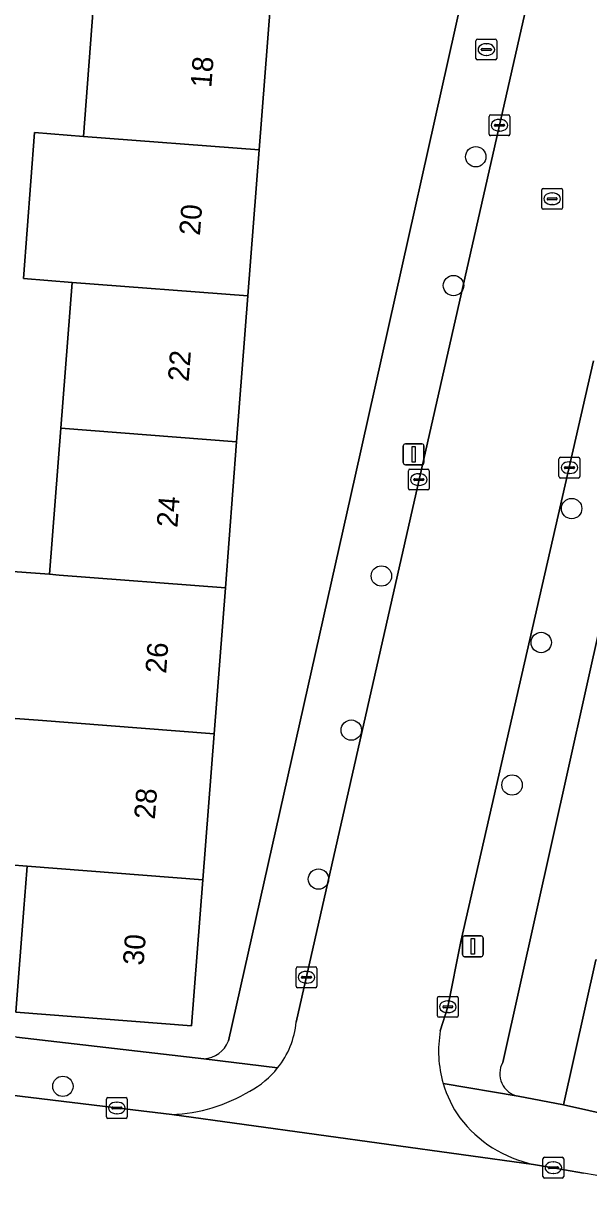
# Model space of a CAD drawing. Extents: x 161838 to 162344, y 381620 to 382160.
# Drawn here: x 161984.1 to 162011.2, y 381777.3 to 381833 of the extents above; entities that cross this region are included whole.
import ezdxf

# ---------------------------------------------------------------- set-up
doc = ezdxf.new("R2010")
doc.units = 0
for name, color, linetype in [('IMGEO_Boom', 7, 'Continuous'), ('IMGEO_Brandkraan', 7, 'Continuous'), ('IMGEO_Erf', 7, 'Continuous'), ('IMGEO_Kolk', 7, 'Continuous'), ('IMGEO_Lichtmast', 7, 'Continuous'), ('IMGEO_Pand', 7, 'Continuous'), ('IMGEO_Pand_nummerreeks', 7, 'Continuous'), ('IMGEO_Rijbaan_lokaal_open', 7, 'Continuous'), ('IMGEO_Rioolput', 7, 'Continuous'), ('IMGEO_Voetpad_open', 7, 'Continuous')]:
    doc.layers.add(name, color=color, linetype=linetype)

msp = doc.modelspace()

# ---------------------------------------------------------------- linework, layer by layer
at = {"layer": 'IMGEO_Boom'}
for centre in [(162005.785, 381826.594), (162004.716, 381820.404), (162010.388, 381809.695), (162001.255, 381806.458), (162008.926, 381803.263), (161999.811, 381799.055), (162007.527, 381796.419), (161998.235, 381791.9), (161985.966, 381781.945)]:
    msp.add_circle(centre, 0.489, dxfattribs=at)
at = {"layer": 'IMGEO_Brandkraan'}
for p, q in [((162005.793, 381831.316), (162005.793, 381832.168)), ((162005.868, 381832.242), (162006.72, 381832.242)), ((162006.281, 381832.022), (162006.306, 381832.022)), ((162006.794, 381832.168), (162006.794, 381831.316)), ((162006.052, 381831.736), (162006.052, 381831.748)), ((162006.49, 381831.699), (162006.092, 381831.699)), ((162006.095, 381831.785), (162006.493, 381831.785)), ((162006.304, 381831.462), (162006.279, 381831.462)), ((162006.536, 381831.748), (162006.536, 381831.736)), ((162006.72, 381831.242), (162005.868, 381831.242))]:
    msp.add_line(p, q, dxfattribs=at)
for points in [[(162005.793, 381831.316), (162005.793, 381832.168)], [(162005.868, 381832.242), (162006.72, 381832.242)], [(162006.794, 381832.168), (162006.794, 381831.316)], [(162006.72, 381831.242), (162005.868, 381831.242)]]:
    msp.add_lwpolyline(points, dxfattribs=at)
for centre, radius, start, end in [((162005.87, 381832.166), 0.0765, 91.552, 178.448), ((162005.87, 381832.166), 0.0765, 91.552, 178.448), ((162006.718, 381832.166), 0.0765, 1.552, 88.448), ((162006.718, 381832.166), 0.0765, 1.552, 88.448), ((162006.092, 381831.745), 0.0403, 85.8775, 175.7526), ((162006.089, 381831.735), 0.0366, 178.938, 274.7102), ((162006.493, 381831.742), 0.043, 264.8664, 352.4533), ((162006.497, 381831.747), 0.0386, 1.7309, 96.639), ((162005.87, 381831.318), 0.0765, 181.552, 268.448), ((162005.87, 381831.318), 0.0765, 181.552, 268.448), ((162006.718, 381831.318), 0.0765, 271.552, 358.448), ((162006.718, 381831.318), 0.0765, 271.552, 358.448)]:
    msp.add_arc(centre, radius, start, end, dxfattribs=at)
for centre, major_axis, ratio, start_param, end_param in [((162006.28, 381831.742), (-0.387, 0.002), 0.722429, 4.712389, 7.853982), ((162006.305, 381831.742), (-0.39, 0.002), 0.717154, 1.570796, 4.712389)]:
    msp.add_ellipse(centre, major_axis=major_axis, ratio=ratio, start_param=start_param, end_param=end_param, dxfattribs=at)
at = {"layer": 'IMGEO_Erf'}
for points in [[(161993.909, 381784.124), (162000, 381811.259), (162006.057, 381838.422), (162012.585, 381866.816)], [(161982.867, 381806.728), (161985.326, 381806.539), (161985.867, 381813.55), (161986.408, 381820.561), (161984.068, 381820.741), (161984.608, 381827.752), (161986.949, 381827.572), (161987.489, 381834.583)], [(161995.929, 381833.933), (161995.389, 381826.922), (161994.848, 381819.911), (161994.307, 381812.899), (161993.766, 381805.889), (161993.225, 381798.877), (161992.684, 381791.867), (161992.143, 381784.853), (161983.703, 381785.505), (161984.088, 381790.491), (161984.228, 381792.307), (161984.244, 381792.516), (161981.789, 381792.705)], [(162044.543, 381799.981), (162042.031, 381801.108), (162037.412, 381803.181), (162036.567, 381801.299), (162036.274, 381800.646), (162035.005, 381801.215), (162035.349, 381801.982), (162035.257, 381802.025), (162033.675, 381798.452), (162031.409, 381799.456), (162032.996, 381803.041), (162032.026, 381803.471), (162033.149, 381806.008), (162030.965, 381806.988), (162033.435, 381812.491), (162032.192, 381813.086), (162018.867, 381816.056), (162015.883, 381816.441), (162014.199, 381815.078), (162007.085, 381783.093)], [(162007.821, 381781.474), (162009.992, 381781.058), (162011.554, 381788.029)], [(161983.732, 381784.311), (161992.738, 381783.267)]]:
    msp.add_lwpolyline(points, dxfattribs=at)
for centre, radius, start, end in [((161992.665, 381784.595), 1.33, 273.1399, 339.2574), ((162008.018, 381782.54), 1.084, 149.35, 259.5432)]:
    msp.add_arc(centre, radius, start, end, dxfattribs=at)
at = {"layer": 'IMGEO_Kolk'}
for p, q in [((162006.499, 381828.606), (162007.351, 381828.606)), ((162006.424, 381827.68), (162006.424, 381828.532)), ((162006.683, 381828.1), (162006.683, 381828.112)), ((162007.121, 381828.063), (162006.723, 381828.063)), ((162006.726, 381828.149), (162007.124, 381828.149)), ((162006.912, 381828.386), (162006.937, 381828.386)), ((162007.167, 381828.112), (162007.167, 381828.1)), ((162007.425, 381828.532), (162007.425, 381827.68)), ((162007.351, 381827.606), (162006.499, 381827.606)), ((162006.935, 381827.826), (162006.91, 381827.826)), ((162009.781, 381811.234), (162009.781, 381812.086)), ((162009.856, 381812.16), (162010.708, 381812.16)), ((162010.269, 381811.94), (162010.294, 381811.94)), ((162010.782, 381812.086), (162010.782, 381811.234)), ((162002.552, 381810.662), (162002.552, 381811.514)), ((162002.627, 381811.588), (162003.479, 381811.588)), ((162003.04, 381811.368), (162003.065, 381811.368)), ((162003.553, 381811.514), (162003.553, 381810.662)), ((162010.04, 381811.654), (162010.04, 381811.666)), ((162010.478, 381811.617), (162010.08, 381811.617)), ((162010.083, 381811.703), (162010.481, 381811.703)), ((162010.292, 381811.38), (162010.267, 381811.38)), ((162010.524, 381811.666), (162010.524, 381811.654)), ((162002.811, 381811.082), (162002.811, 381811.094)), ((162003.249, 381811.045), (162002.851, 381811.045)), ((162002.854, 381811.131), (162003.252, 381811.131)), ((162003.063, 381810.808), (162003.038, 381810.808)), ((162003.295, 381811.094), (162003.295, 381811.082)), ((162010.708, 381811.16), (162009.856, 381811.16)), ((162003.479, 381810.588), (162002.627, 381810.588)), ((161997.16, 381786.758), (161997.16, 381787.61)), ((161997.235, 381787.684), (161998.087, 381787.684)), ((161997.648, 381787.464), (161997.673, 381787.464)), ((161998.161, 381787.61), (161998.161, 381786.758)), ((161997.419, 381787.178), (161997.419, 381787.19)), ((161997.857, 381787.141), (161997.459, 381787.141)), ((161997.462, 381787.227), (161997.86, 381787.227)), ((161997.671, 381786.904), (161997.646, 381786.904)), ((161997.903, 381787.19), (161997.903, 381787.178)), ((161998.087, 381786.684), (161997.235, 381786.684)), ((162004.021, 381786.265), (162004.873, 381786.265)), ((162003.946, 381785.339), (162003.946, 381786.191)), ((162004.205, 381785.759), (162004.205, 381785.771)), ((162004.643, 381785.722), (162004.245, 381785.722)), ((162004.248, 381785.808), (162004.646, 381785.808)), ((162004.434, 381786.045), (162004.459, 381786.045)), ((162004.689, 381785.771), (162004.689, 381785.759)), ((162004.947, 381786.191), (162004.947, 381785.339)), ((162004.873, 381785.265), (162004.021, 381785.265)), ((162004.457, 381785.485), (162004.432, 381785.485)), ((161988.055, 381780.481), (161988.055, 381781.333)), ((161988.13, 381781.407), (161988.982, 381781.407)), ((161989.056, 381781.333), (161989.056, 381780.481)), ((161988.314, 381780.901), (161988.314, 381780.913)), ((161988.752, 381780.864), (161988.354, 381780.864)), ((161988.357, 381780.95), (161988.755, 381780.95)), ((161988.543, 381781.187), (161988.568, 381781.187)), ((161988.798, 381780.913), (161988.798, 381780.901)), ((161988.982, 381780.407), (161988.13, 381780.407)), ((161988.566, 381780.627), (161988.541, 381780.627)), ((162009.009, 381777.612), (162009.009, 381778.464)), ((162009.084, 381778.538), (162009.936, 381778.538)), ((162010.01, 381778.464), (162010.01, 381777.612)), ((162009.268, 381778.032), (162009.268, 381778.044)), ((162009.706, 381777.995), (162009.308, 381777.995)), ((162009.311, 381778.081), (162009.709, 381778.081)), ((162009.497, 381778.318), (162009.522, 381778.318)), ((162009.752, 381778.044), (162009.752, 381778.032)), ((162009.936, 381777.538), (162009.084, 381777.538)), ((162009.52, 381777.758), (162009.495, 381777.758))]:
    msp.add_line(p, q, dxfattribs=at)
for points in [[(162006.499, 381828.606), (162007.351, 381828.606)], [(162006.424, 381827.68), (162006.424, 381828.532)], [(162007.425, 381828.532), (162007.425, 381827.68)], [(162007.351, 381827.606), (162006.499, 381827.606)], [(162009.781, 381811.234), (162009.781, 381812.086)], [(162009.856, 381812.16), (162010.708, 381812.16)], [(162010.782, 381812.086), (162010.782, 381811.234)], [(162002.552, 381810.662), (162002.552, 381811.514)], [(162002.627, 381811.588), (162003.479, 381811.588)], [(162003.553, 381811.514), (162003.553, 381810.662)], [(162010.708, 381811.16), (162009.856, 381811.16)], [(162003.479, 381810.588), (162002.627, 381810.588)], [(161997.16, 381786.758), (161997.16, 381787.61)], [(161997.235, 381787.684), (161998.087, 381787.684)], [(161998.161, 381787.61), (161998.161, 381786.758)], [(161998.087, 381786.684), (161997.235, 381786.684)], [(162004.021, 381786.265), (162004.873, 381786.265)], [(162003.946, 381785.339), (162003.946, 381786.191)], [(162004.947, 381786.191), (162004.947, 381785.339)], [(162004.873, 381785.265), (162004.021, 381785.265)], [(161988.055, 381780.481), (161988.055, 381781.333)], [(161988.13, 381781.407), (161988.982, 381781.407)], [(161989.056, 381781.333), (161989.056, 381780.481)], [(161988.982, 381780.407), (161988.13, 381780.407)], [(162009.009, 381777.612), (162009.009, 381778.464)], [(162009.084, 381778.538), (162009.936, 381778.538)], [(162010.01, 381778.464), (162010.01, 381777.612)], [(162009.936, 381777.538), (162009.084, 381777.538)]]:
    msp.add_lwpolyline(points, dxfattribs=at)
for centre, radius, start, end in [((162006.501, 381828.53), 0.0765, 91.552, 178.448), ((162006.501, 381828.53), 0.0765, 91.552, 178.448), ((162007.349, 381828.53), 0.0765, 1.552, 88.448), ((162007.349, 381828.53), 0.0765, 1.552, 88.448), ((162006.723, 381828.109), 0.0403, 85.8775, 175.7526), ((162006.72, 381828.099), 0.0366, 178.938, 274.7102), ((162007.124, 381828.106), 0.043, 264.8664, 352.4533), ((162007.128, 381828.111), 0.0386, 1.7309, 96.639), ((162006.501, 381827.682), 0.0765, 181.552, 268.448), ((162006.501, 381827.682), 0.0765, 181.552, 268.448), ((162007.349, 381827.682), 0.0765, 271.552, 358.448), ((162007.349, 381827.682), 0.0765, 271.552, 358.448), ((162009.858, 381812.084), 0.0765, 91.552, 178.448), ((162009.858, 381812.084), 0.0765, 91.552, 178.448), ((162010.706, 381812.084), 0.0765, 1.552, 88.448), ((162010.706, 381812.084), 0.0765, 1.552, 88.448), ((162002.629, 381811.512), 0.0765, 91.552, 178.448), ((162002.629, 381811.512), 0.0765, 91.552, 178.448), ((162003.477, 381811.512), 0.0765, 1.552, 88.448), ((162003.477, 381811.512), 0.0765, 1.552, 88.448), ((162010.08, 381811.663), 0.0403, 85.8775, 175.7526), ((162010.077, 381811.653), 0.0366, 178.938, 274.7102), ((162010.481, 381811.66), 0.043, 264.8664, 352.4533), ((162010.485, 381811.665), 0.0386, 1.7309, 96.639), ((162002.851, 381811.091), 0.0403, 85.8775, 175.7526), ((162002.848, 381811.081), 0.0366, 178.938, 274.7102), ((162003.252, 381811.088), 0.043, 264.8664, 352.4533), ((162003.256, 381811.093), 0.0386, 1.7309, 96.639), ((162009.858, 381811.236), 0.0765, 181.552, 268.448), ((162009.858, 381811.236), 0.0765, 181.552, 268.448), ((162010.706, 381811.236), 0.0765, 271.552, 358.448), ((162010.706, 381811.236), 0.0765, 271.552, 358.448), ((162002.629, 381810.664), 0.0765, 181.552, 268.448), ((162002.629, 381810.664), 0.0765, 181.552, 268.448), ((162003.477, 381810.664), 0.0765, 271.552, 358.448), ((162003.477, 381810.664), 0.0765, 271.552, 358.448), ((161997.237, 381787.608), 0.0765, 91.552, 178.448), ((161997.237, 381787.608), 0.0765, 91.552, 178.448), ((161998.085, 381787.608), 0.0765, 1.552, 88.448), ((161998.085, 381787.608), 0.0765, 1.552, 88.448), ((161997.459, 381787.187), 0.0403, 85.8775, 175.7526), ((161997.456, 381787.177), 0.0366, 178.938, 274.7102), ((161997.86, 381787.184), 0.043, 264.8664, 352.4533), ((161997.864, 381787.189), 0.0386, 1.7309, 96.639), ((161997.237, 381786.76), 0.0765, 181.552, 268.448), ((161997.237, 381786.76), 0.0765, 181.552, 268.448), ((161998.085, 381786.76), 0.0765, 271.552, 358.448), ((161998.085, 381786.76), 0.0765, 271.552, 358.448), ((162004.023, 381786.189), 0.0765, 91.552, 178.448), ((162004.023, 381786.189), 0.0765, 91.552, 178.448), ((162004.871, 381786.189), 0.0765, 1.552, 88.448), ((162004.871, 381786.189), 0.0765, 1.552, 88.448), ((162004.245, 381785.768), 0.0403, 85.8775, 175.7526), ((162004.242, 381785.758), 0.0366, 178.938, 274.7102), ((162004.646, 381785.765), 0.043, 264.8664, 352.4533), ((162004.65, 381785.77), 0.0386, 1.7309, 96.639), ((162004.023, 381785.341), 0.0765, 181.552, 268.448), ((162004.023, 381785.341), 0.0765, 181.552, 268.448), ((162004.871, 381785.341), 0.0765, 271.552, 358.448), ((162004.871, 381785.341), 0.0765, 271.552, 358.448), ((161988.132, 381781.331), 0.0765, 91.552, 178.448), ((161988.132, 381781.331), 0.0765, 91.552, 178.448), ((161988.98, 381781.331), 0.0765, 1.552, 88.448), ((161988.98, 381781.331), 0.0765, 1.552, 88.448), ((161988.354, 381780.91), 0.0403, 85.8775, 175.7526), ((161988.351, 381780.9), 0.0366, 178.938, 274.7102), ((161988.755, 381780.907), 0.043, 264.8664, 352.4533), ((161988.759, 381780.912), 0.0386, 1.7309, 96.639), ((161988.132, 381780.483), 0.0765, 181.552, 268.448), ((161988.132, 381780.483), 0.0765, 181.552, 268.448), ((161988.98, 381780.483), 0.0765, 271.552, 358.448), ((161988.98, 381780.483), 0.0765, 271.552, 358.448), ((162009.086, 381778.462), 0.0765, 91.552, 178.448), ((162009.086, 381778.462), 0.0765, 91.552, 178.448), ((162009.934, 381778.462), 0.0765, 1.552, 88.448), ((162009.934, 381778.462), 0.0765, 1.552, 88.448), ((162009.308, 381778.041), 0.0403, 85.8775, 175.7526), ((162009.305, 381778.031), 0.0366, 178.938, 274.7102), ((162009.709, 381778.038), 0.043, 264.8664, 352.4533), ((162009.713, 381778.043), 0.0386, 1.7309, 96.639), ((162009.086, 381777.614), 0.0765, 181.552, 268.448), ((162009.086, 381777.614), 0.0765, 181.552, 268.448), ((162009.934, 381777.614), 0.0765, 271.552, 358.448), ((162009.934, 381777.614), 0.0765, 271.552, 358.448)]:
    msp.add_arc(centre, radius, start, end, dxfattribs=at)
for centre, major_axis, ratio, start_param, end_param in [((162006.911, 381828.106), (-0.387, 0.002), 0.722429, 4.712389, 7.853982), ((162006.936, 381828.106), (-0.39, 0.002), 0.717154, 1.570796, 4.712389), ((162010.268, 381811.66), (-0.387, 0.002), 0.722429, 4.712389, 7.853982), ((162010.293, 381811.66), (-0.39, 0.002), 0.717154, 1.570796, 4.712389), ((162003.039, 381811.088), (-0.387, 0.002), 0.722429, 4.712389, 7.853982), ((162003.064, 381811.088), (-0.39, 0.002), 0.717154, 1.570796, 4.712389), ((161997.647, 381787.184), (-0.387, 0.002), 0.722429, 4.712389, 7.853982), ((161997.672, 381787.184), (-0.39, 0.002), 0.717154, 1.570796, 4.712389), ((162004.433, 381785.765), (-0.387, 0.002), 0.722429, 4.712389, 7.853982), ((162004.458, 381785.765), (-0.39, 0.002), 0.717154, 1.570796, 4.712389), ((161988.542, 381780.907), (-0.387, 0.002), 0.722429, 4.712389, 7.853982), ((161988.567, 381780.907), (-0.39, 0.002), 0.717154, 1.570796, 4.712389), ((162009.496, 381778.038), (-0.387, 0.002), 0.722429, 4.712389, 7.853982), ((162009.521, 381778.038), (-0.39, 0.002), 0.717154, 1.570796, 4.712389)]:
    msp.add_ellipse(centre, major_axis=major_axis, ratio=ratio, start_param=start_param, end_param=end_param, dxfattribs=at)
at = {"layer": 'IMGEO_Lichtmast'}
for p, q in [((162002.308, 381811.904), (162002.308, 381812.704)), ((162002.308, 381812.704), (162002.308, 381811.904)), ((162002.408, 381812.804), (162003.198, 381812.804)), ((162003.198, 381812.804), (162002.408, 381812.804)), ((162003.298, 381812.704), (162003.298, 381811.904)), ((162003.298, 381811.904), (162003.298, 381812.704)), ((162003.198, 381811.804), (162002.408, 381811.804)), ((162002.408, 381811.804), (162003.198, 381811.804)), ((162005.149, 381788.272), (162005.149, 381789.072)), ((162005.149, 381789.072), (162005.149, 381788.272)), ((162005.249, 381789.172), (162006.039, 381789.172)), ((162006.039, 381789.172), (162005.249, 381789.172)), ((162006.139, 381789.072), (162006.139, 381788.272)), ((162006.139, 381788.272), (162006.139, 381789.072)), ((162006.039, 381788.172), (162005.249, 381788.172)), ((162005.249, 381788.172), (162006.039, 381788.172))]:
    msp.add_line(p, q, dxfattribs=at)
for points in [[(162002.728, 381812.679), (162002.878, 381812.679), (162002.878, 381811.929), (162002.728, 381811.929), (162002.728, 381812.679)], [(162005.569, 381789.047), (162005.719, 381789.047), (162005.719, 381788.297), (162005.569, 381788.297), (162005.569, 381789.047)]]:
    msp.add_lwpolyline(points, dxfattribs=at)
for centre, start, end in [((162002.408, 381812.704), 90, 180), ((162002.408, 381812.704), 90, 180), ((162003.198, 381812.704), 0, 90), ((162003.198, 381812.704), 360, 90), ((162002.408, 381811.904), 180, 270), ((162002.408, 381811.904), 180, 270), ((162003.198, 381811.904), 270, 0), ((162003.198, 381811.904), 270, 0), ((162005.249, 381789.072), 90, 180), ((162005.249, 381789.072), 90, 180), ((162006.039, 381789.072), 0, 90), ((162006.039, 381789.072), 360, 90), ((162005.249, 381788.272), 180, 270), ((162005.249, 381788.272), 180, 270), ((162006.039, 381788.272), 270, 0), ((162006.039, 381788.272), 270, 0)]:
    msp.add_arc(centre, 0.1, start, end, dxfattribs=at)
at = {"layer": 'IMGEO_Pand'}
for points in [[(161995.389, 381826.922), (161995.929, 381833.933), (161987.489, 381834.583), (161986.949, 381827.572)], [(161995.389, 381826.922), (161986.949, 381827.572), (161984.608, 381827.752), (161984.068, 381820.741), (161986.408, 381820.561), (161994.848, 381819.911)], [(161994.848, 381819.911), (161986.408, 381820.561), (161985.867, 381813.55), (161994.307, 381812.899)], [(161994.307, 381812.899), (161985.867, 381813.55), (161985.326, 381806.539), (161985.792, 381806.503), (161993.766, 381805.889)], [(161993.766, 381805.889), (161985.792, 381806.503), (161985.326, 381806.539), (161982.867, 381806.728), (161982.328, 381799.716), (161984.785, 381799.527), (161993.225, 381798.877)], [(161984.785, 381799.527), (161982.328, 381799.716), (161981.789, 381792.705), (161984.244, 381792.516), (161992.684, 381791.867), (161993.225, 381798.877)], [(161984.244, 381792.516), (161984.228, 381792.307), (161984.088, 381790.491), (161983.703, 381785.505), (161992.143, 381784.853), (161992.684, 381791.867)], [(162011.554, 381788.029), (162009.992, 381781.058), (162018.222, 381779.214), (162019.784, 381786.185)]]:
    msp.add_lwpolyline(points, close=True, dxfattribs=at)
at = {"layer": 'IMGEO_Rijbaan_lokaal_open'}
for points in [[(162017.975, 381876.532), (162010.118, 381842.239), (161997.168, 381785.034)], [(162004.084, 381784.61), (162004.447, 381785.765), (162005.071, 381788.907), (162011.439, 381816.796)], [(162010.959, 381777.779), (162009.14, 381778.097), (162008.56, 381778.199), (161991.196, 381780.587), (161988.923, 381780.862), (161972.91, 381782.799), (161963.403, 381783.98), (161942.624, 381786.599)], [(161991.196, 381780.587), (162008.56, 381778.199)]]:
    msp.add_lwpolyline(points, dxfattribs=at)
for centre, radius, start, end in [((161992.973, 381785.448), 4.215, 321.5631, 354.3602), ((162009.557, 381783.641), 5.558, 169.9636, 196.2502), ((161992.969, 381785.45), 4.219, 297.848, 321.5857), ((162009.535, 381783.649), 5.539, 196.39, 215.4551), ((161990.849, 381788.492), 7.913, 272.5133, 301.1321), ((162009.77, 381784.027), 5.952, 217.1052, 258.2716), ((162004.162, 381739.93), 38.455, 66.4256, 79.8199)]:
    msp.add_arc(centre, radius, start, end, dxfattribs=at)
at = {"layer": 'IMGEO_Rioolput'}
for p, q in [((162008.95, 381824.147), (162008.95, 381824.999)), ((162009.025, 381825.073), (162009.877, 381825.073)), ((162009.438, 381824.853), (162009.463, 381824.853)), ((162009.951, 381824.999), (162009.951, 381824.147)), ((162009.209, 381824.567), (162009.209, 381824.579)), ((162009.647, 381824.53), (162009.249, 381824.53)), ((162009.252, 381824.616), (162009.65, 381824.616)), ((162009.461, 381824.293), (162009.436, 381824.293)), ((162009.693, 381824.579), (162009.693, 381824.567)), ((162009.877, 381824.073), (162009.025, 381824.073))]:
    msp.add_line(p, q, dxfattribs=at)
for points in [[(162008.95, 381824.147), (162008.95, 381824.999)], [(162009.025, 381825.073), (162009.877, 381825.073)], [(162009.951, 381824.999), (162009.951, 381824.147)], [(162009.877, 381824.073), (162009.025, 381824.073)]]:
    msp.add_lwpolyline(points, dxfattribs=at)
for centre, radius, start, end in [((162009.027, 381824.997), 0.0765, 91.552, 178.448), ((162009.027, 381824.997), 0.0765, 91.552, 178.448), ((162009.875, 381824.997), 0.0765, 1.552, 88.448), ((162009.875, 381824.997), 0.0765, 1.552, 88.448), ((162009.027, 381824.149), 0.0765, 181.552, 268.448), ((162009.027, 381824.149), 0.0765, 181.552, 268.448), ((162009.249, 381824.576), 0.0403, 85.8775, 175.7526), ((162009.246, 381824.566), 0.0366, 178.938, 274.7102), ((162009.65, 381824.573), 0.043, 264.8664, 352.4533), ((162009.654, 381824.578), 0.0386, 1.7309, 96.639), ((162009.875, 381824.149), 0.0765, 271.552, 358.448), ((162009.875, 381824.149), 0.0765, 271.552, 358.448)]:
    msp.add_arc(centre, radius, start, end, dxfattribs=at)
for centre, major_axis, ratio, start_param, end_param in [((162009.437, 381824.573), (-0.387, 0.002), 0.722429, 4.712389, 7.853982), ((162009.462, 381824.573), (-0.39, 0.002), 0.717154, 1.570796, 4.712389)]:
    msp.add_ellipse(centre, major_axis=major_axis, ratio=ratio, start_param=start_param, end_param=end_param, dxfattribs=at)
at = {"layer": 'IMGEO_Voetpad_open'}
for points in [[(162016.258, 381885.569), (162005.739, 381900.791), (162004.132, 381899.684), (162004.242, 381899.525), (162013.985, 381885.418), (162015.122, 381883.128), (162015.619, 381881.528), (162015.663, 381880.219), (162015.506, 381878.919), (162012.585, 381866.816), (162006.057, 381838.422), (162000, 381811.259), (161993.909, 381784.124)], [(161997.168, 381785.034), (162010.118, 381842.239)], [(162011.439, 381816.796), (162005.071, 381788.907), (162004.447, 381785.765), (162004.084, 381784.61)], [(162007.085, 381783.093), (162014.199, 381815.078)], [(161992.738, 381783.267), (161983.732, 381784.311), (161973.243, 381785.519), (161972.91, 381782.799), (161988.923, 381780.862), (161991.196, 381780.587)], [(161996.275, 381782.828), (161992.738, 381783.267)], [(161992.738, 381783.267), (161996.275, 381782.828)], [(162004.221, 381782.086), (162007.821, 381781.474)], [(162074.49, 381753.282), (162068.219, 381756.057), (162068.579, 381756.936), (162067.446, 381757.401), (162067.371, 381757.236), (162065.115, 381758.257), (162064.835, 381757.639), (162061.101, 381759.332), (162056.054, 381761.616), (162050.052, 381764.333), (162049.942, 381764.37), (162048.674, 381764.793), (162048.513, 381764.865), (162045.047, 381766.421), (162038.572, 381769.363), (162032.236, 381772.242), (162025.763, 381775.183), (162026.727, 381777.305), (162025.108, 381777.668), (162022.125, 381778.338), (162018.222, 381779.214), (162009.992, 381781.058), (162007.821, 381781.474), (162004.221, 381782.086)], [(162008.56, 381778.199), (162009.14, 381778.097), (162010.959, 381777.779)]]:
    msp.add_lwpolyline(points, dxfattribs=at)
for centre, radius, start, end in [((161992.973, 381785.448), 4.215, 321.5631, 354.3602), ((162009.557, 381783.641), 5.558, 169.9636, 196.2502), ((161992.665, 381784.595), 1.33, 273.1399, 339.2574), ((162008.018, 381782.54), 1.084, 149.35, 259.5432), ((161992.969, 381785.45), 4.219, 297.848, 321.5857), ((162009.535, 381783.649), 5.539, 196.39, 215.4551), ((161990.849, 381788.492), 7.913, 272.5133, 301.1321), ((162009.77, 381784.027), 5.952, 217.1052, 258.2716), ((162004.162, 381739.93), 38.455, 66.4256, 79.8199)]:
    msp.add_arc(centre, radius, start, end, dxfattribs=at)

# ---------------------------------------------------------------- texts
at = {"layer": 'IMGEO_Pand_nummerreeks'}
for s, p in [('18', (161993.09, 381829.888)), ('20', (161992.543, 381822.787)), ('22', (161992.001, 381815.77)), ('24', (161991.46, 381808.762)), ('26', (161990.919, 381801.751)), ('28', (161990.379, 381794.743)), ('30', (161989.838, 381787.732))]:
    msp.add_text(s, height=1, rotation=85.5884, dxfattribs=at).set_placement(p)

doc.saveas('drawing.dxf')
